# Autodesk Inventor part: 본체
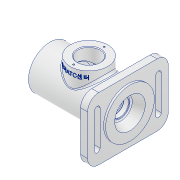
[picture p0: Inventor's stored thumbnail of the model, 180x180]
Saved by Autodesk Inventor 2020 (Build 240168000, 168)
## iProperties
Created: 2021-07
Part Number: 본체
Material: 알루미늄 6061
Document SubType Name: Modeling
Designer: MIRAE
Density: 2.7 g/cm^3
Appearance: 알루미늄 - 평지
Mass: 738.429 g
Surface Area: 646.405 cm^2
Volume: 273.492 cm^3
Author: MIRAE
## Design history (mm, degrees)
sketch "스케치1"
  geometry: L1 (-57.5, 0)-(57.5, 0); L2 (-57.5, 31)-(57.5, 31); L3 (-57.5, 31)-(-57.5, 0); L4 (57.5, 31)-(57.5, 0); 1 further point
  constraints: 8 end point, 2 horizontal, 2 vertical, 1 midpoint
  dimensions: "d0" = 115 distance of L1.start L1.end; "d1" = 57.5 distance of point (0, 0) L1.start; "d2" = 62 diameter of L2 L1
revolve "회전1" sketch "스케치1" stored, may be unused: angle "d3" = 90 deg
sketch "스케치4"
  geometry: C1 r 31 at (0, 0) reference; 2 further points
  constraints: 1 coincident
hole "구멍1" sketch "스케치4" at (0, 0) diameter "d4" = 40.3762; stored, may be unused: countersink angle "d8" = 90 deg, drill point angle "d10" = 0 deg; dims "d5" = 84, "d6" = 4, "d7" = 2, "d9" = 9
sketch "스케치6"
  geometry: C1 r 24 at (0, 0); 1 further point
  constraints: 1 centre point, 1 coincident
  dimensions: "d11" = 48 diameter of C1
extrude "돌출1" cut sketch "스케치6" distance "d12" = 3; taper "d13" = 0 deg
sketch "스케치7"
  geometry: C1 r 20 at (0, 0); 1 further point
  constraints: 1 centre point, 1 coincident
  dimensions: "d14" = 40 diameter of C1
extrude "돌출2" cut sketch "스케치7" distance "d15" = 9; taper "d16" = 0 deg
sketch "스케치8"
  geometry: C1 r 17.5 at (0, 0); 1 further point
  constraints: 1 centre point, 1 coincident
  dimensions: "d17" = 35 diameter of C1
extrude "돌출3" cut sketch "스케치8" distance "d18" = 3.25; taper "d19" = 0 deg
sketch "스케치9"
  geometry: C1 r 18.5 at (0, 0); 1 further point
  constraints: 1 centre point, 1 coincident
  dimensions: "d20" = 37 diameter of C1
extrude "돌출4" cut sketch "스케치9" distance "d21" = 1.75; taper "d22" = 0 deg
sketch "스케치10"
  geometry: C1 r 17.5 at (0, 0); 1 further point
  constraints: 1 centre point, 1 coincident
  dimensions: "d23" = 35 diameter of C1
extrude "돌출5" cut sketch "스케치10" distance "d24" = 11; taper "d25" = 0 deg
sketch "스케치11"
  geometry: C1 r 26 at (0, 0); 1 further point
  constraints: 1 centre point, 1 coincident
  dimensions: "d26" = 52 diameter of C1
extrude "돌출6" cut sketch "스케치11" distance "d27" = 38; taper "d28" = 0 deg
sketch "스케치12"
  geometry: C1 r 17.5 at (0, 0); 1 further point
  constraints: 1 centre point, 1 coincident
  dimensions: "d29" = 35 diameter of C1
extrude "돌출7" cut sketch "스케치12" distance "d30" = 11; taper "d31" = 0 deg
sketch "스케치13"
  geometry: C1 r 16 at (0, 0); 1 further point
  constraints: 1 centre point, 1 coincident
  dimensions: "d32" = 32 diameter of C1
extrude "돌출8" cut sketch "스케치13" distance "d33" = 5; taper "d34" = 0 deg
sketch "스케치14"
  geometry: C1 r 10 at (0, 0); 1 further point
  constraints: 1 centre point, 1 coincident
  dimensions: "d35" = 20 diameter of C1
extrude "돌출9" cut sketch "스케치14" distance "d36" = 2.7; taper "d37" = 0 deg
sketch "스케치15"
  geometry: C1 r 12.5 at (0, 0); 1 further point
  constraints: 1 centre point, 1 coincident
  dimensions: "d38" = 25 diameter of C1
extrude "돌출10" cut sketch "스케치15" distance "d39" = 6.6; taper "d40" = 0 deg
sketch "스케치17"
  geometry: C1 r 12.5 at (0, 0); 1 further point
  constraints: 1 centre point, 1 coincident
  dimensions: "d47" = 25 diameter of C1
extrude "돌출11" cut sketch "스케치17" distance "d48" = 0.7; taper "d49" = 30 deg
sketch "스케치19"
  geometry: L1 (43.5, 12.904)-(43.5, -12.904) reference; L2 (43.5, 0)-(57.5, 0); L3 (57.5, -31)-(57.5, 31) reference; L4 (43.5, 12.904)-(43.5, 16); L5 (43.5, 16)-(57.5, 22); 1 further point
  constraints: 6 end point, 2 midpoint, 1 point on line, 1 vertical
  dimensions: "d50" = 44 diameter of L5.end L2; "d51" = 32 diameter of L4.end L2
revolve "회전4" sketch "스케치19" stored, may be unused: angle "d52" = 360 deg
node "작업 평면1"
sketch "스케치20"
  geometry: L1 (57.5, 31)-(57.5, -31) reference; C1 r 27 at (1.5, 0); 1 further point
  constraints: 1 centre point, 1 horizontal alignment, 1 midpoint
  dimensions: "d95" = 56 distance from line of C1.centre L1; "d96" = 54 diameter of C1
extrude "돌출12" join sketch "스케치20" stored distance "d55" = 0.7; taper "d56" = 0 deg
sketch "스케치21"
  geometry: L1 (-56, -31)-(-56, 31) reference; C1 r 16 at (0, 0); 1 further point
  constraints: 1 centre point, 1 horizontal alignment, 1 midpoint
  dimensions: "d97" = 56 distance from line of C1.centre L1; "d98" = 32 diameter of C1
extrude "돌출13" cut sketch "스케치21" distance "d58" = 43.45; taper "d59" = 0 deg
sketch "스케치24"
  geometry: L1 (-56, -31)-(-56, 31) reference; A1 r 22 centre (0, 0) between (0, 22) and (0, -22); 1 further point
  constraints: 2 point on circle, 2 vertical alignment, 1 centre point, 1 horizontal alignment, 1 midpoint
  dimensions: "d99" = 56 distance from line of A1.centre L1; "d100" = 44 diameter of A1
hole "구멍2" sketch "스케치24" at (0, 22), (0, -22) diameter "d73" = 2.459; stored, may be unused: countersink angle "d77" = 90 deg, drill point angle "d79" = 118 deg; dims "d74" = 6, "d75" = 4, "d76" = 2, "d78" = 8
node "작업 평면4"
sketch "스케치25"
  geometry: L1 (27, 0)-(-27, 0) reference; 2 further points
  constraints: 1 vertical alignment, 1 other
  dimensions: "d80" = 8 distance from line of point (1.5, -8) L1
feature "엠보싱1" sketch "스케치25" dims "d81" = 0.5, "d82" = 0
chamfer "모따기1" distance "d83" = 1; stored, may be unused: second distance "d84" = 2, angle "d85" = 45 deg
chamfer "모따기2" distance "d86" = 1; stored, may be unused: second distance "d87" = 2, angle "d88" = 45 deg
chamfer "모따기3" distance "d89" = 1; stored, may be unused: second distance "d90" = 2, angle "d91" = 45 deg
fillet "모깎기2" dims "d92" = 0.3
fillet "모깎기3" dims "d93" = 3
fillet "모깎기4" dims "d94" = 3
node "작업 평면7"
sketch "스케치26"
  geometry: L1 (-45, -58)-(45, -58); L2 (45, -58)-(45, 58); L3 (45, 58)-(-45, 58); L4 (-45, 58)-(-45, -58); L5 (-45, -58)-(45, 58); L6 (45, -58)-(-45, 58); C1 r 10 at (0, 0) reference; 1 further point
  constraints: 12 end point, 2 midpoint, 2 parallel, 1 horizontal, 1 perpendicular
  dimensions: "d103" = 90 distance of L3.end L2.end; "d104" = 116 distance of L2.end L1.end
extrude "돌출16" join sketch "스케치26" distance "d105" = 10; taper "d106" = 0 deg
fillet "모깎기5" dims "d107" = 16
sketch "스케치27"
  geometry: L1 (-44, 25)-(-44, -25); L2 (-48, 25)-(-48, -25); L3 (-40, -25)-(-40, 25); A1 r 4 centre (-44, 25) between (-40, 25) and (-48, 25); A2 r 4 centre (-44, -25) between (-48, -25) and (-40, -25); 2 further points
  constraints: 8 end point, 4 point on circle, 4 tangent, 2 centre point, 1 horizontal alignment, 1 midpoint, 1 parallel, 1 vertical
  dimensions: "d108" = 50 distance of L1.start L1.end; "d109" = 8 diameter of A2; "d110" = 44 distance from line of point (0, 0) L1
extrude "돌출17" cut sketch "스케치27" extent not by distance; stored distance "d111" = 0; taper "d112" = 0 deg
fillet "모깎기6" dims "d113" = 3
node "작업 평면8"
sketch "스케치29"
  geometry: C1 r 35 at (0, 0); 1 further point
  constraints: 1 centre point, 1 coincident
  dimensions: "d117" = 70 diameter of C1
extrude "돌출18" join sketch "스케치29" distance "d118" = 3; taper "d119" = 0 deg
sketch "스케치28"
  geometry: L1 (44.5, -16.258)-(44.5, 16.258) reference; L2 (44.5, 0)-(57.5, 0); L3 (57.5, 22)-(57.5, -22) reference; L4 (54.5, 20.714)-(57.5, 22) reference; L5 (44.5, 16.258)-(57.5, 22); L6 (54.5, 20.714)-(57.5, 22) reference; 3 further points
  constraints: 4 end point, 2 midpoint
  dimensions: "d115" = 44 diameter of L3.start L2 (derived)
revolve "회전5" sketch "스케치28" stored, may be unused: angle "d114" = 360 deg
node "솔리드1"
mirror "미러2"
feature "A9D066F2-1C7D-4E18-AEED-F7BC21143FA4" dims "d73" = 2.459, "d74" = 6, "d75" = 4, "d76" = 2, "d77" = 90 deg, "d78" = 8, "d79" = 118 deg
other parameters: "d53" = 42, "d102" = 44.5, "d116" = 57.5
